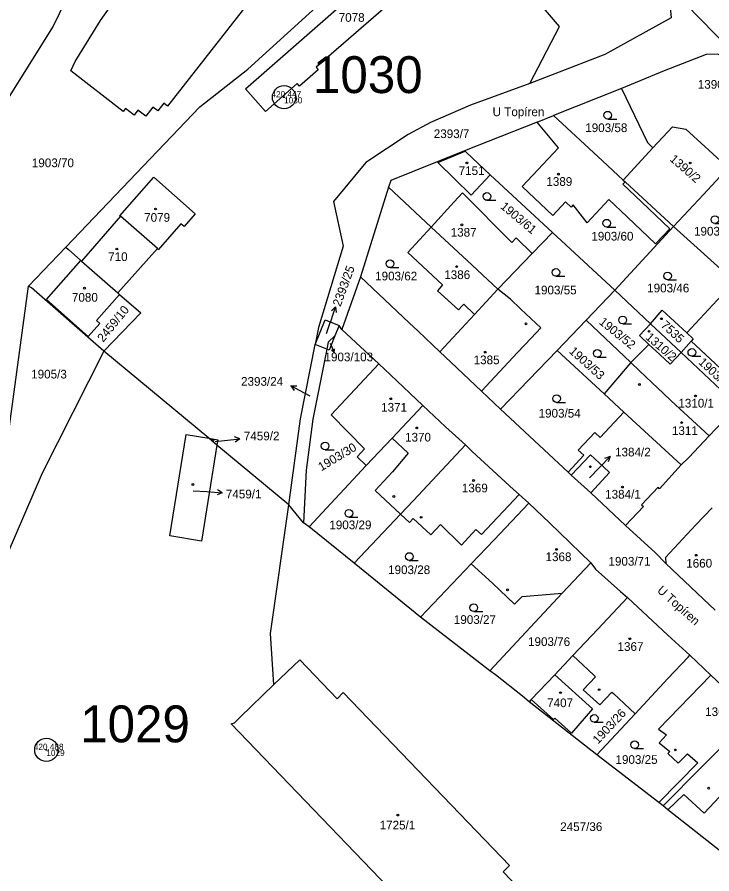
# Model space of a CAD drawing. Extents: x -667048 to -665920, y -1108425 to -1107247.
# Drawn here: x -666539 to -666403.4, y -1107579.1 to -1107411.8 of the extents above; entities that cross this region are included whole.
import ezdxf

# ---------------------------------------------------------------- set-up
doc = ezdxf.new("R2010")
doc.units = 0
for name, color, linetype in [('Default', 7, 'Continuous'), ('Hranice parcel', 7, 'Continuous'), ('Parcelní čísla', 7, 'Continuous'), ('Pop_ PČ_ popisy', 7, 'Continuous'), ('Vrstva 1', 7, 'Continuous'), ('Vrstva 60', 7, 'Continuous'), ('Vrstva 61', 7, 'Continuous'), ('Značky budov', 7, 'Continuous'), ('Značky kultur', 7, 'Continuous')]:
    doc.layers.add(name, color=color, linetype=linetype)

# ---------------------------------------------------------------- blocks, each defined once
blk = doc.blocks.new('3.041')
at = {"layer": 'Default'}
blk.add_line((8, 0), (1758, 0), dxfattribs=at)
blk.add_circle((8, 750), 750, dxfattribs=at)
blk = doc.blocks.new('4.021')
at = {"layer": 'Default'}
blk.add_circle((-7, 1), 175, dxfattribs=at)
blk = doc.blocks.new('10291')
at = {"layer": 'Default'}
for p, q in [((0, 3001), (-500, 2001)), ((0, 1), (0, 3001)), ((0, 3001), (500, 2001))]:
    blk.add_line(p, q, dxfattribs=at)

msp = doc.modelspace()

# ---------------------------------------------------------------- linework, layer by layer
at = {"layer": 'Hranice parcel'}
for points in [[(-666529.58, -1107365.05), (-666528.65, -1107363.83), (-666527.38, -1107362.27), (-666526, -1107360.78), (-666525.33, -1107360.09), (-666524.5, -1107359.49), (-666523.62, -1107358.97), (-666522.71, -1107358.57), (-666521.79, -1107358.26), (-666520.82, -1107358.06), (-666519.82, -1107357.98), (-666518.83, -1107357.97), (-666517.84, -1107358.06), (-666516.83, -1107358.15), (-666507.97, -1107359.8), (-666506.97, -1107359.94), (-666504.96, -1107360.19), (-666498, -1107360.88), (-666497.35, -1107364.63), (-666512.39, -1107381.51), (-666518.15, -1107389.63), (-666528.43, -1107406.29), (-666531.96, -1107413.61), (-666543.57, -1107432.05)], [(-666529.53, -1107456.78), (-666503.31, -1107429.33), (-666493.96, -1107422.02), (-666451, -1107382.94), (-666442.47, -1107378.83)], [(-666490.55, -1107430.26), (-666494.44, -1107425.82), (-666453.35, -1107389.86), (-666449.38, -1107394.36), (-666457.45, -1107401.4), (-666457.02, -1107401.89), (-666461.75, -1107406.01), (-666462.18, -1107405.52), (-666480.66, -1107421.64), (-666480.23, -1107422.13), (-666483.9, -1107425.32), (-666484.32, -1107424.83), (-666490.55, -1107430.26)], [(-666483.55, -1107395.84), (-666509.64, -1107429.21), (-666510.4, -1107428.64), (-666511.57, -1107430.14), (-666512.52, -1107429.41), (-666513.89, -1107431.19), (-666515.43, -1107429.99), (-666516.18, -1107430.96), (-666517.82, -1107429.69)], [(-666438.94, -1107424.82), (-666433.13, -1107413.64), (-666436.63, -1107409.59), (-666423.96, -1107398.67), (-666422.41, -1107397.33), (-666420.5, -1107399.81)], [(-666517.82, -1107429.69), (-666518.28, -1107430.28), (-666528.55, -1107422.32), (-666527.7, -1107420.48), (-666522.72, -1107412.49), (-666517.55, -1107405.08)], [(-666411.38, -1107406.25), (-666399.89, -1107418.1)], [(-666411.67, -1107408.61), (-666411.32, -1107412), (-666424.31, -1107419.11), (-666438.94, -1107424.82)], [(-666399.98, -1107420.12), (-666402.24, -1107419.07), (-666404.5, -1107419.14), (-666412.69, -1107422.36), (-666421.03, -1107425.75)], [(-666438.94, -1107424.82), (-666450.48, -1107429.05), (-666458.29, -1107432.4), (-666462.64, -1107434.77), (-666470.93, -1107440.2), (-666477.27, -1107447.86), (-666475.37, -1107456.58), (-666480.15, -1107472.45), (-666480.81, -1107475.77)], [(-666421.03, -1107425.75), (-666434.3, -1107431.08)], [(-666421.03, -1107425.75), (-666415.94, -1107436.3), (-666414.94, -1107437.39)], [(-666437.51, -1107432.35), (-666434.3, -1107431.08)], [(-666434.3, -1107431.08), (-666424.71, -1107439.93), (-666420.68, -1107443.66)], [(-666437.51, -1107432.35), (-666451.67, -1107437.92)], [(-666430.87, -1107448.92), (-666431.98, -1107447.91), (-666434.4, -1107450.57), (-666440.43, -1107444.92), (-666433.35, -1107437.35), (-666437.24, -1107432.68), (-666437.51, -1107432.35)], [(-666414.94, -1107437.39), (-666411.08, -1107433.28), (-666408.44, -1107433.75), (-666400.23, -1107441.24)], [(-666414.94, -1107437.39), (-666420.68, -1107443.66)], [(-666451.67, -1107437.92), (-666466.06, -1107443.74), (-666466.48, -1107445.07)], [(-666446.64, -1107442.61), (-666450.38, -1107446.63), (-666456.91, -1107440.25), (-666451.57, -1107438.01)], [(-666451.67, -1107437.92), (-666451.57, -1107438.01)], [(-666451.57, -1107438.01), (-666451.36, -1107438.22), (-666446.64, -1107442.61)], [(-666446.64, -1107442.61), (-666434.52, -1107453.89)], [(-666405.01, -1107446.47), (-666400.23, -1107441.24)], [(-666518.82, -1107450.73), (-666518.93, -1107450.63), (-666512.35, -1107443.11), (-666504.22, -1107450.22), (-666506.43, -1107452.71), (-666507.03, -1107452.18), (-666511.49, -1107457.29), (-666511.6, -1107457)], [(-666420.33, -1107443.98), (-666420.77, -1107444.46), (-666417.13, -1107447.92), (-666411.62, -1107453.18), (-666414.42, -1107456.11), (-666419.9, -1107450.84), (-666423.49, -1107447.43)], [(-666420.68, -1107443.66), (-666420.33, -1107443.98)], [(-666410.88, -1107452.71), (-666420.33, -1107443.98)], [(-666466.48, -1107445.07), (-666471.95, -1107462.56)], [(-666466.48, -1107445.07), (-666458.21, -1107452.88)], [(-666458.21, -1107452.88), (-666453.69, -1107447.94), (-666452.06, -1107446.17)], [(-666452.06, -1107446.17), (-666442.43, -1107455.85), (-666441.59, -1107454.96), (-666438.45, -1107457.97)], [(-666423.49, -1107447.43), (-666427.71, -1107451.99), (-666430.47, -1107448.48), (-666430.87, -1107448.92)], [(-666410.88, -1107452.71), (-666405.01, -1107446.47)], [(-666518.82, -1107450.73), (-666526.43, -1107459.49)], [(-666511.6, -1107457), (-666518.82, -1107450.73)], [(-666458.21, -1107452.88), (-666462.74, -1107457.82), (-666455.97, -1107464.1), (-666456.97, -1107465.28), (-666452.86, -1107469.02), (-666452.11, -1107468.2), (-666451.83, -1107467.89), (-666449.71, -1107469.88)], [(-666445.17, -1107464.96), (-666451.16, -1107459.36), (-666458.21, -1107452.88)], [(-666422.35, -1107465.17), (-666410.88, -1107452.71)], [(-666410.88, -1107452.71), (-666398.99, -1107463.45)], [(-666438.45, -1107457.97), (-666434.52, -1107453.89)], [(-666434.52, -1107453.89), (-666422.35, -1107465.17)], [(-666536.79, -1107464.38), (-666529.53, -1107456.78)], [(-666529.53, -1107456.78), (-666529, -1107457.24), (-666526.54, -1107459.39)], [(-666519.35, -1107465.67), (-666511.6, -1107457)], [(-666518.99, -1107465.98), (-666523.48, -1107471.11), (-666522.87, -1107471.64), (-666525.11, -1107474.2), (-666533.27, -1107466.97), (-666526.54, -1107459.39)], [(-666526.54, -1107459.39), (-666526.43, -1107459.49)], [(-666526.43, -1107459.49), (-666519.35, -1107465.67)], [(-666438.45, -1107457.97), (-666445.17, -1107464.96)], [(-666471.95, -1107462.56), (-666475.63, -1107472.82)], [(-666456.47, -1107477.22), (-666460.75, -1107473.17), (-666462.46, -1107471.55), (-666471.95, -1107462.56)], [(-666546.86, -1107538.25), (-666536.79, -1107464.38)], [(-666522.09, -1107477.04), (-666536.21, -1107464.73), (-666536.79, -1107464.38)], [(-666398.99, -1107463.45), (-666408.3, -1107473.49)], [(-666518.99, -1107465.98), (-666514.84, -1107469.61), (-666522.09, -1107477.04)], [(-666519.35, -1107465.67), (-666518.99, -1107465.98)], [(-666445.17, -1107464.96), (-666449.71, -1107469.88)], [(-666448.35, -1107484.86), (-666441.32, -1107477.36), (-666438.64, -1107474.52), (-666436.76, -1107472.52), (-666440.65, -1107468.86), (-666442.71, -1107466.91), (-666445.17, -1107464.96)], [(-666422.35, -1107465.17), (-666427.95, -1107471.01)], [(-666422.35, -1107465.17), (-666415.39, -1107471.71)], [(-666415.39, -1107471.71), (-666413.06, -1107469.04), (-666408.3, -1107473.49)], [(-666480.81, -1107475.77), (-666478.85, -1107470.94), (-666476.14, -1107472.05)], [(-666449.71, -1107469.88), (-666456.47, -1107477.22)], [(-666427.95, -1107471.01), (-666433.58, -1107476.94)], [(-666427.95, -1107471.01), (-666419.21, -1107479.31)], [(-666476.14, -1107472.05), (-666476.96, -1107474.06)], [(-666475.63, -1107472.82), (-666476.14, -1107472.05)], [(-666475.63, -1107472.82), (-666468.42, -1107479.57)], [(-666415.39, -1107471.71), (-666417.53, -1107474), (-666415.68, -1107475.74)], [(-666409.39, -1107477.35), (-666415.39, -1107471.71)], [(-666476.96, -1107474.06), (-666478.31, -1107475.31), (-666478.58, -1107476.67)], [(-666476.96, -1107474.06), (-666478.11, -1107476.87), (-666478.58, -1107476.67)], [(-666408.3, -1107473.49), (-666407.05, -1107474.65), (-666407.43, -1107475.09)], [(-666485.96, -1107507.09), (-666483.7, -1107490.26), (-666480.81, -1107475.77)], [(-666478.58, -1107476.67), (-666480.81, -1107475.77)], [(-666415.68, -1107475.74), (-666419.21, -1107479.31)], [(-666409.39, -1107477.35), (-666411.53, -1107479.62), (-666413.56, -1107477.72), (-666415.68, -1107475.74)], [(-666409.39, -1107477.35), (-666407.43, -1107475.09)], [(-666407.43, -1107475.09), (-666403.72, -1107478.57), (-666396.3, -1107485.53)], [(-666522.09, -1107477.04), (-666534.11, -1107500.88), (-666542.69, -1107520.69), (-666546.86, -1107538.25)], [(-666501.61, -1107494.08), (-666522.09, -1107477.04)], [(-666478.58, -1107476.67), (-666481.27, -1107490.34), (-666482.59, -1107500.32), (-666483.08, -1107510.58)], [(-666448.35, -1107484.86), (-666454.31, -1107479.24), (-666456.47, -1107477.22)], [(-666433.58, -1107476.94), (-666444.67, -1107488.37)], [(-666424.41, -1107485.41), (-666433.58, -1107476.94)], [(-666398.33, -1107487.74), (-666409.39, -1107477.35)], [(-666468.42, -1107479.57), (-666477.72, -1107489.52), (-666471.2, -1107496.12), (-666472.62, -1107497.68), (-666470.87, -1107499.39)], [(-666468.42, -1107479.57), (-666466.15, -1107481.7), (-666459.79, -1107487.68)], [(-666419.21, -1107479.31), (-666424.41, -1107485.41)], [(-666419.21, -1107479.31), (-666417.51, -1107480.93), (-666415.01, -1107483.23), (-666412.88, -1107485.24), (-666411.3, -1107486.74), (-666403.88, -1107493.6)], [(-666444.67, -1107488.37), (-666448.35, -1107484.86)], [(-666420.56, -1107488.97), (-666424.41, -1107485.41)], [(-666459.79, -1107487.68), (-666465.81, -1107494.04)], [(-666459.79, -1107487.68), (-666455.37, -1107491.83), (-666451.48, -1107495.38)], [(-666403.88, -1107493.6), (-666399.79, -1107489.29), (-666398.33, -1107487.74)], [(-666444.67, -1107488.37), (-666431.45, -1107500.68)], [(-666431.45, -1107500.68), (-666428.37, -1107497.38), (-666429.46, -1107496.38), (-666426.24, -1107492.92), (-666425.16, -1107493.92), (-666420.56, -1107488.97)], [(-666420.56, -1107488.97), (-666409.39, -1107499.29)], [(-666500, -1107495.41), (-666503, -1107514.14), (-666509.22, -1107513.15), (-666506.02, -1107493.35), (-666501.61, -1107494.08)], [(-666500, -1107495.41), (-666501.61, -1107494.08)], [(-666501.61, -1107494.08), (-666499.84, -1107494.37), (-666500, -1107495.41)], [(-666470.87, -1107499.39), (-666465.81, -1107494.04)], [(-666465.81, -1107494.04), (-666462.68, -1107497), (-666465.74, -1107500.63), (-666469.11, -1107504.27), (-666464.16, -1107508.89)], [(-666409.39, -1107499.29), (-666407.9, -1107497.86), (-666403.88, -1107493.6)], [(-666485.96, -1107507.09), (-666500, -1107495.41)], [(-666451.48, -1107495.38), (-666461.64, -1107506.23), (-666464.16, -1107508.89)], [(-666451.48, -1107495.38), (-666450.17, -1107496.63), (-666442.1, -1107504.07), (-666440.99, -1107505.06)], [(-666427.04, -1107504.75), (-666423.4, -1107500.74), (-666424.52, -1107499.64), (-666427.08, -1107497.28), (-666430.82, -1107501.26)], [(-666470.87, -1107499.39), (-666482.01, -1107511.36)], [(-666409.39, -1107499.29), (-666413.58, -1107503.92), (-666413.9, -1107503.62), (-666417.09, -1107507.07), (-666416.72, -1107507.38), (-666420.25, -1107511.11)], [(-666430.82, -1107501.26), (-666431.45, -1107500.68)], [(-666427.04, -1107504.75), (-666430.82, -1107501.26)], [(-666420.25, -1107511.11), (-666427.04, -1107504.75)], [(-666464.16, -1107508.89), (-666462.44, -1107510.5), (-666461.72, -1107509.73), (-666458.23, -1107512.9), (-666456.39, -1107510.92), (-666452.25, -1107514.94), (-666449.43, -1107511.88), (-666448.36, -1107512.87), (-666440.99, -1107505.06)], [(-666440.99, -1107505.06), (-666439.13, -1107506.78)], [(-666488.88, -1107542.16), (-666489.54, -1107532.21), (-666485.96, -1107507.09)], [(-666483.08, -1107510.58), (-666485.96, -1107507.09)], [(-666439.13, -1107506.78), (-666445.89, -1107513.89), (-666450.38, -1107518.62)], [(-666439.13, -1107506.78), (-666435.05, -1107510.61), (-666427.03, -1107518.4)], [(-666403.35, -1107507.63), (-666406.53, -1107511), (-666412.45, -1107517.33), (-666412.36, -1107518.53)], [(-666464.16, -1107508.89), (-666473.24, -1107518.45)], [(-666482.01, -1107511.36), (-666483.08, -1107510.58)], [(-666473.24, -1107518.45), (-666482.01, -1107511.36)], [(-666412.36, -1107518.53), (-666414.37, -1107516.47), (-666420.25, -1107511.11)], [(-666460.28, -1107529.04), (-666473.24, -1107518.45)], [(-666450.38, -1107518.62), (-666460.28, -1107529.04)], [(-666450.38, -1107518.62), (-666446.19, -1107522.37), (-666441.9, -1107526.5), (-666440.42, -1107524.99), (-666432.6, -1107524.31)], [(-666432.6, -1107524.31), (-666427.03, -1107518.4)], [(-666427.03, -1107518.4), (-666426.09, -1107519.65), (-666421.22, -1107524.03), (-666419.86, -1107525.17)], [(-666402.71, -1107527.67), (-666405.08, -1107525.41), (-666412.36, -1107518.53)], [(-666446.72, -1107539.47), (-666432.6, -1107524.31)], [(-666419.86, -1107525.17), (-666425.63, -1107531.33), (-666430.5, -1107536.49)], [(-666419.86, -1107525.17), (-666411.95, -1107532.53), (-666407.68, -1107536.43)], [(-666446.72, -1107539.47), (-666460.28, -1107529.04)], [(-666430.5, -1107536.49), (-666434.07, -1107540.26)], [(-666430.5, -1107536.49), (-666426.4, -1107540.33), (-666426.08, -1107540.64), (-666428.5, -1107543.19), (-666425.26, -1107546.14), (-666422.9, -1107543.65), (-666422.61, -1107543.92), (-666418.35, -1107547.86)], [(-666418.35, -1107547.86), (-666411.96, -1107541.01), (-666408.03, -1107536.79), (-666407.68, -1107536.43)], [(-666407.68, -1107536.43), (-666403.56, -1107540.31)], [(-666488.88, -1107542.16), (-666483.8, -1107537.34), (-666476.53, -1107544.93)], [(-666439.07, -1107545.55), (-666440.32, -1107544.46), (-666445.65, -1107540.28), (-666446.72, -1107539.47)], [(-666438.63, -1107545.08), (-666434.07, -1107540.26)], [(-666434.07, -1107540.26), (-666426.69, -1107546.94), (-666430.81, -1107551.67), (-666434.07, -1107548.75), (-666434.31, -1107549.01), (-666438.63, -1107545.08)], [(-666403.56, -1107540.31), (-666413.79, -1107550.91), (-666412.25, -1107552.01), (-666413.68, -1107553.54), (-666411.62, -1107555.26), (-666411.96, -1107555.62), (-666409.97, -1107557.55), (-666408.17, -1107555.7), (-666406.12, -1107557.48), (-666413.74, -1107565.21)], [(-666403.56, -1107540.31), (-666402.43, -1107541.42), (-666395.81, -1107547.63)], [(-666453.69, -1107595.16), (-666497.2, -1107549.84), (-666496.6, -1107549.66), (-666495.44, -1107548.56), (-666488.88, -1107542.16)], [(-666476.53, -1107544.93), (-666475.34, -1107543.74), (-666442.88, -1107577.49), (-666444.13, -1107578.76), (-666440.95, -1107582.08)], [(-666438.63, -1107545.08), (-666439.07, -1107545.55)], [(-666425.83, -1107555.87), (-666439.07, -1107545.55)], [(-666418.35, -1107547.86), (-666425.83, -1107555.87)], [(-666395.81, -1107547.63), (-666401.82, -1107554.71), (-666405.33, -1107558.26), (-666412.87, -1107565.88)], [(-666411.96, -1107566.6), (-666408.87, -1107563.61), (-666404.89, -1107567.3), (-666402.86, -1107565.11), (-666401.07, -1107563.18), (-666399.4, -1107561.31), (-666398.34, -1107562.25), (-666390.04, -1107553.76), (-666389.76, -1107553.33)], [(-666413.74, -1107565.21), (-666425.83, -1107555.87)], [(-666412.87, -1107565.88), (-666413.74, -1107565.21)], [(-666411.96, -1107566.6), (-666412.87, -1107565.88)], [(-666399.78, -1107576.19), (-666411.96, -1107566.6)]]:
    msp.add_lwpolyline(points, dxfattribs=at)
at = {"layer": 'Pop_ PČ_ popisy'}
for points in [[(-666478.59, -1107473.63), (-666477.8, -1107471.26)], [(-666481.81, -1107485.87), (-666482.92, -1107485.26)], [(-666500.34, -1107494.73), (-666498.5, -1107494.52)], [(-666427.29, -1107501.82), (-666425.35, -1107499.79)], [(-666504.62, -1107504.32), (-666501.95, -1107504.49)]]:
    msp.add_lwpolyline(points, dxfattribs=at)
at = {"layer": 'Vrstva 1'}
for p, q in [((-666487.05, -1107427.49), (-666486.75, -1107427.49)), ((-666533.45, -1107554.92), (-666533.15, -1107554.92))]:
    msp.add_line(p, q, dxfattribs=at)
for centre in [(-666486.9, -1107427.49), (-666533.3, -1107554.92)]:
    msp.add_circle(centre, 2.27, dxfattribs=at)
at = {"layer": 'Vrstva 60'}
for p, q in [((-666486.9, -1107427.49), (-666486.9, -1107427.49)), ((-666533.3, -1107554.92), (-666533.3, -1107554.92))]:
    msp.add_line(p, q, dxfattribs=at)

# ---------------------------------------------------------------- block references
at = {"layer": 'Pop_ PČ_ popisy'}
for p, xscale, yscale, rotation in [((-666477.8, -1107471.26), 0.0010000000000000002, 0.0010000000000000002, -17.99999992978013), ((-666477.88, -1107475.48), 0.0006700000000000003, 0.0006700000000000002, -156.99999994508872), ((-666482.92, -1107485.26), 0.001, 0.0010000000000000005, 61.00000001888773), ((-666498.5, -1107494.52), 0.001, 0.0009999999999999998, -84.00000003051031), ((-666425.35, -1107499.79), 0.0010000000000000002, 0.0010000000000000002, -44.00000000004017), ((-666501.95, -1107504.49), 0.0010000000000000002, 0.0010000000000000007, -93.99999998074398)]:
    msp.add_blockref('10291', p, dxfattribs=dict(at, xscale=xscale, yscale=yscale, rotation=rotation))
at = {"layer": 'Značky budov', "xscale": 0.0010000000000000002, "yscale": 0.0010000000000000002}
for p in [(-666451.19, -1107440.31), (-666407.59, -1107440.32), (-666433.34, -1107442.5), (-666511.97, -1107449.31), (-666452.19, -1107452.41), (-666519.54, -1107457.12), (-666453.19, -1107460.55), (-666525.86, -1107464.76), (-666413.23, -1107470.73), (-666439.66, -1107471.72), (-666415.65, -1107473.19), (-666447.61, -1107477.29), (-666417.53, -1107483.57), (-666466.06, -1107486.36), (-666406.58, -1107485.81), (-666409.27, -1107491.02), (-666460.99, -1107492.06), (-666500.77, -1107494.45), (-666427.1, -1107499.64), (-666504.68, -1107503.11), (-666449.89, -1107502.33), (-666420.84, -1107503.6), (-666465.47, -1107505.46), (-666460.15, -1107509.52), (-666433.69, -1107515.78), (-666406.42, -1107516.92), (-666443.26, -1107523.67), (-666419.39, -1107533.22), (-666425.4, -1107543.17), (-666432.93, -1107543.75), (-666410.51, -1107554.94), (-666404, -1107562.39), (-666464.68, -1107567.65)]:
    msp.add_blockref('4.021', p, dxfattribs=at)
at = {"layer": 'Značky kultur', "xscale": 0.0010000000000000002, "yscale": 0.0010000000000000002}
for p in [(-666423.72, -1107431.74), (-666447.31, -1107447.61), (-666402.8, -1107452.14), (-666423.91, -1107452.83), (-666466.22, -1107460.76), (-666433.83, -1107462.44), (-666412.04, -1107463.12), (-666420.8, -1107471.74), (-666425.76, -1107478.26), (-666407.3, -1107478.07), (-666433.7, -1107487.07), (-666478.9, -1107496.33), (-666474.24, -1107509.48), (-666462.46, -1107517.92), (-666449.87, -1107527.91), (-666426.35, -1107549.53), (-666418.47, -1107554.68)]:
    msp.add_blockref('3.041', p, dxfattribs=at)

# ---------------------------------------------------------------- texts
at = {"layer": 'Parcelní čísla'}
for s, p in [('7078', (-666476.23, -1107412.75)), ('1390/1', (-666406.13, -1107425.82)), ('1903/58', (-666428.1, -1107434.29)), ('2393/7', (-666457.67, -1107435.46)), ('1903/70', (-666536.13, -1107441.14)), ('7151', (-666452.81, -1107442.67)), ('1389', (-666435.69, -1107444.79)), ('7079', (-666514.21, -1107451.8)), ('1903/35', (-666406.87, -1107454.5)), ('1387', (-666454.37, -1107454.71)), ('1903/60', (-666426.91, -1107455.47)), ('710', (-666521.23, -1107459.47)), ('1903/62', (-666469.12, -1107463.25)), ('1386', (-666455.62, -1107462.99)), ('1903/55', (-666438, -1107465.98)), ('1903/46', (-666416.01, -1107465.59)), ('7080', (-666528.31, -1107467.41)), ('1903/103', (-666479, -1107479.05)), ('1385', (-666449.89, -1107479.62)), ('1905/3', (-666536.26, -1107482.4)), ('2393/24', (-666495.29, -1107483.82)), ('1310/1', (-666409.92, -1107488.07)), ('1371', (-666467.95, -1107488.88)), ('1903/54', (-666437.21, -1107490.04)), ('7459/2', (-666494.75, -1107494.48)), ('1370', (-666463.28, -1107494.72)), ('1311', (-666411.18, -1107493.44)), ('1384/2', (-666422.28, -1107497.62)), ('1369', (-666452.19, -1107504.64)), ('7459/1', (-666498.26, -1107505.82)), ('1384/1', (-666424.22, -1107505.86)), ('1903/29', (-666478.06, -1107511.84)), ('1368', (-666435.85, -1107518.07)), ('1903/71', (-666423.57, -1107518.95)), ('1660', (-666408.39, -1107519.33)), ('1903/28', (-666466.59, -1107520.6)), ('1903/27', (-666453.75, -1107530.33)), ('1903/76', (-666439.27, -1107534.64)), ('1367', (-666421.8, -1107535.6)), ('7407', (-666435.54, -1107546.58)), ('1366', (-666404.69, -1107548.32)), ('1903/25', (-666422.2, -1107557.66)), ('1725/1', (-666468.24, -1107570.46)), ('2457/36', (-666432.99, -1107570.77))]:
    msp.add_text(s, height=1.7, dxfattribs=at).set_placement(p)
for s, rotation, p in [('1390/2', 319, (-666411.74, -1107439.77)), ('1903/61', 320, (-666444.8, -1107449.04)), ('2393/25', 70, (-666475.88, -1107468.48)), ('2459/10', 51, (-666522.2, -1107475.43)), ('1903/52', 321, (-666425.54, -1107471.62)), ('7535', 317, (-666413.46, -1107472.17)), ('1310/2', 319, (-666416.45, -1107474.57)), ('1903/53', 318, (-666431.38, -1107477.27)), ('1903/109', 317, (-666406.14, -1107479.39)), ('1903/30', 31, (-666479.62, -1107500.55)), ('1903/26', 47, (-666425.6, -1107553.9))]:
    msp.add_text(s, height=1.7, rotation=rotation, dxfattribs=at).set_placement(p)
at = {"layer": 'Pop_ PČ_ popisy'}
msp.add_text('U Topíren', height=1.7, dxfattribs=at).set_placement((-666446.19, -1107431.18))
msp.add_text('U Topíren', height=1.7, rotation=318, dxfattribs=at).set_placement((-666414.19, -1107523.97))
at = {"layer": 'Vrstva 1'}
for s, p in [('1030', (-666481.26, -1107426.67)), ('1029', (-666526.7, -1107553.45))]:
    msp.add_text(s, height=7.2, dxfattribs=at).set_placement(p)
at = {"layer": 'Vrstva 60'}
for s, p in [('1030', (-666486.9, -1107428.69)), ('1029', (-666533.3, -1107556.12))]:
    msp.add_text(s, height=1.2, dxfattribs=at).set_placement(p)
at = {"layer": 'Vrstva 61'}
for s, p in [('420.447', (-666489.35, -1107427.49)), ('420.488', (-666535.75, -1107554.92))]:
    msp.add_text(s, height=1.2, dxfattribs=at).set_placement(p)

doc.saveas('drawing.dxf')
